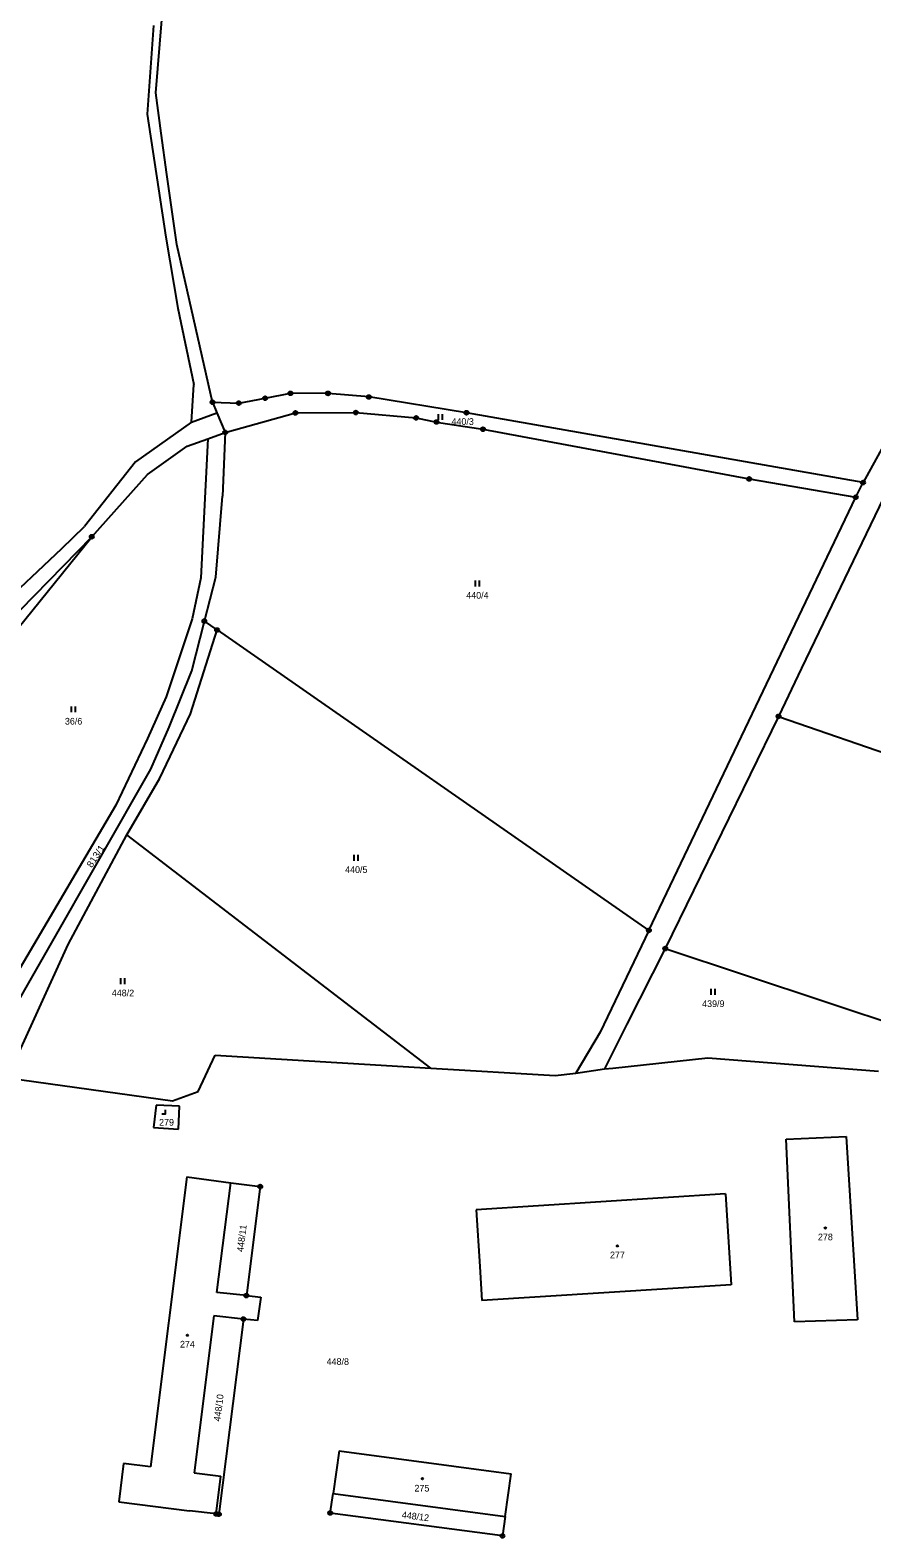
# Model space of a CAD drawing. Extents: x -739410 to -735662, y -942282 to -940043.
# Drawn here: x -737598.7 to -737384.4, y -941577.7 to -941193.9 of the extents above; entities that cross this region are included whole.
import ezdxf
from ezdxf.enums import TextEntityAlignment as Align

# ---------------------------------------------------------------- set-up
doc = ezdxf.new("R2010")
doc.units = 0
doc.header["$LTSCALE"] = 0.68
for name, color, linetype, lineweight in [('1', 7, 'Continuous', 25), ('3', 7, 'Continuous', 25), ('5', 7, 'Continuous', 25), ('8', 7, 'Continuous', 25)]:
    doc.layers.add(name, color=color, linetype=linetype, lineweight=lineweight)
doc.layers.add('2', color=7, linetype='Continuous')

msp = doc.modelspace()

# ---------------------------------------------------------------- linework, layer by layer
at = {"layer": '1'}
for p, q in [((-737567.25, -941192.75), (-737568.89, -941215.34)), ((-737566.68, -941209.91), (-737565.18, -941191.33)), ((-737565.29, -941220.14), (-737566.68, -941209.91)), ((-737568.89, -941215.34), (-737564.15, -941246.6)), ((-737563.9, -941230.66), (-737565.29, -941220.14)), ((-737561.32, -941248.49), (-737563.9, -941230.66)), ((-737564.15, -941246.6), (-737561.08, -941264.67)), ((-737552.23, -941288.66), (-737561.32, -941248.49)), ((-737561.08, -941264.67), (-737557, -941284.11)), ((-737557.62, -941293.73), (-737557, -941284.11)), ((-737538.85, -941287.63), (-737532.42, -941286.38)), ((-737522.84, -941286.4), (-737532.42, -941286.38)), ((-737512.43, -941287.32), (-737522.84, -941286.4)), ((-737552.23, -941288.66), (-737551.11, -941291.34)), ((-737552.23, -941288.66), (-737545.56, -941288.87)), ((-737545.56, -941288.87), (-737538.85, -941287.63)), ((-737487.61, -941291.32), (-737512.43, -941287.32)), ((-737557.62, -941293.73), (-737571.83, -941303.81)), ((-737557.62, -941293.73), (-737551.11, -941291.34)), ((-737551.11, -941291.34), (-737549.01, -941296.33)), ((-737549.01, -941296.33), (-737531.14, -941291.37)), ((-737531.14, -941291.37), (-737515.75, -941291.28)), ((-737515.75, -941291.28), (-737500.42, -941292.65)), ((-737500.42, -941292.65), (-737495.23, -941293.69)), ((-737495.23, -941293.69), (-737483.4, -941295.53)), ((-737386.64, -941309.11), (-737487.61, -941291.32)), ((-737558.7, -941299.8), (-737553.41, -941297.93)), ((-737553.41, -941297.93), (-737555.2, -941333.38)), ((-737553.41, -941297.93), (-737549.01, -941296.33)), ((-737549.01, -941296.33), (-737549.68, -941312.57)), ((-737483.4, -941295.53), (-737415.63, -941308.18)), ((-737380.49, -941297.99), (-737386.64, -941309.11)), ((-737568.81, -941307.04), (-737558.7, -941299.8)), ((-737571.83, -941303.81), (-737584.85, -941320.25)), ((-737582.99, -941322.88), (-737568.81, -941307.04)), ((-737415.63, -941308.18), (-737388.51, -941312.84)), ((-737388.51, -941312.84), (-737386.64, -941309.11)), ((-737551.42, -941333.21), (-737549.68, -941312.57)), ((-737441.17, -941423.08), (-737388.51, -941312.84)), ((-737381.43, -941312.98), (-737402.36, -941356.33)), ((-737590.57, -941325.9), (-737584.85, -941320.25)), ((-737604.75, -941345.26), (-737582.99, -941322.88)), ((-737603.59, -941348.41), (-737582.99, -941322.88)), ((-737608.18, -941342.43), (-737590.57, -941325.9)), ((-737555.2, -941333.38), (-737557.44, -941343.8)), ((-737554.32, -941344.36), (-737551.42, -941333.21)), ((-737557.44, -941343.8), (-737564.06, -941363.65)), ((-737557.52, -941357.03), (-737554.32, -941344.36)), ((-737551.08, -941346.62), (-737554.32, -941344.36)), ((-737557.82, -941367.93), (-737551.08, -941346.62)), ((-737551.08, -941346.62), (-737441.17, -941423.08)), ((-737563.32, -941371.36), (-737557.52, -941357.03)), ((-737402.36, -941356.33), (-737408.16, -941368.6)), ((-737564.06, -941363.65), (-737568.77, -941374.27)), ((-737567.98, -941382.05), (-737563.32, -941371.36)), ((-737565.69, -941384.32), (-737557.82, -941367.93)), ((-737408.16, -941368.6), (-737436.99, -941427.7)), ((-737408.16, -941368.6), (-737318.79, -941399.47)), ((-737568.77, -941374.27), (-737576.89, -941391.18)), ((-737606.95, -941450.23), (-737567.98, -941382.05)), ((-737574.08, -941398.77), (-737565.69, -941384.32)), ((-737576.89, -941391.18), (-737601.21, -941432.59)), ((-737589.02, -941426.68), (-737574.08, -941398.77)), ((-737496.66, -941458.16), (-737574.08, -941398.77)), ((-737441.17, -941423.08), (-737453.54, -941448.98)), ((-737604.45, -941460.6), (-737589.02, -941426.68)), ((-737436.99, -941427.7), (-737446.76, -941446.95)), ((-737436.99, -941427.7), (-737374.65, -941448.39)), ((-737446.76, -941446.95), (-737452.43, -941458.32)), ((-737453.54, -941448.98), (-737459.74, -941459.43)), ((-737555.92, -941464.07), (-737551.58, -941454.86)), ((-737551.58, -941454.86), (-737496.66, -941458.16)), ((-737450.31, -941458.14), (-737426.13, -941455.54)), ((-737426.13, -941455.54), (-737382.68, -941458.93)), ((-737496.66, -941458.16), (-737465.03, -941460.03)), ((-737452.43, -941458.32), (-737450.31, -941458.14)), ((-737604.45, -941460.6), (-737562.44, -941466.42)), ((-737562.44, -941466.42), (-737555.92, -941464.07)), ((-737566.59, -941467.59), (-737567.26, -941473.26)), ((-737560.66, -941467.84), (-737566.59, -941467.59)), ((-737560.89, -941473.71), (-737560.66, -941467.84)), ((-737567.26, -941473.26), (-737560.89, -941473.71)), ((-737406.26, -941476.19), (-737390.95, -941475.55)), ((-737404.13, -941522.75), (-737406.26, -941476.19)), ((-737390.95, -941475.55), (-737388.09, -941522.19)), ((-737558.77, -941485.83), (-737568.02, -941559.59)), ((-737558.77, -941485.83), (-737547.55, -941487.33)), ((-737551.11, -941515.24), (-737547.55, -941487.33)), ((-737547.55, -941487.33), (-737540.09, -941488.29)), ((-737540.09, -941488.29), (-737543.63, -941516.03)), ((-737421.65, -941490.16), (-737485.13, -941494.18)), ((-737421.65, -941490.16), (-737420.2, -941513.26)), ((-737485.13, -941494.18), (-737484.21, -941508.62)), ((-737484.21, -941508.62), (-737483.68, -941517.28)), ((-737420.2, -941513.26), (-737483.68, -941517.28)), ((-737543.63, -941516.03), (-737551.11, -941515.24)), ((-737543.63, -941516.03), (-737539.97, -941516.41)), ((-737539.97, -941516.41), (-737540.76, -941522.41)), ((-737551.87, -941521.2), (-737556.95, -941561.15)), ((-737544.38, -941522.02), (-737551.87, -941521.2)), ((-737544.38, -941522.02), (-737550.63, -941571.69)), ((-737540.76, -941522.41), (-737544.38, -941522.02)), ((-737388.09, -941522.19), (-737404.13, -941522.75)), ((-737519.99, -941555.56), (-737521.56, -941566.38)), ((-737519.99, -941555.56), (-737476.2, -941561.43)), ((-737574.9, -941558.76), (-737576.11, -941568.51)), ((-737568.02, -941559.59), (-737574.9, -941558.76)), ((-737556.95, -941561.15), (-737550.14, -941562.02)), ((-737551.28, -941571.61), (-737550.14, -941562.02)), ((-737477.77, -941572.25), (-737476.2, -941561.43)), ((-737522.28, -941571.37), (-737521.56, -941566.38)), ((-737521.56, -941566.38), (-737477.77, -941572.25)), ((-737576.11, -941568.51), (-737558.08, -941570.8)), ((-737551.28, -941571.61), (-737558.08, -941570.8)), ((-737550.63, -941571.69), (-737551.28, -941571.61)), ((-737478.44, -941577.19), (-737522.28, -941571.37)), ((-737477.77, -941572.25), (-737478.44, -941577.19))]:
    msp.add_line(p, q, dxfattribs=at)
msp.add_lwpolyline([(-737465.03, -941460.03), (-737459.74, -941459.43), (-737452.43, -941458.32)], dxfattribs=at)
at = {"layer": '3'}
for p, q in [((-737494.711, -941293.15), (-737494.711, -941291.65)), ((-737493.71, -941293.15), (-737493.71, -941291.65)), ((-737485.321, -941335.51), (-737485.321, -941334.01)), ((-737484.32, -941335.51), (-737484.32, -941334.01)), ((-737588.121, -941367.57), (-737588.121, -941366.07)), ((-737587.12, -941367.57), (-737587.12, -941366.07)), ((-737516.161, -941405.34), (-737516.161, -941403.84)), ((-737515.16, -941405.34), (-737515.16, -941403.84)), ((-737575.551, -941436.74), (-737575.551, -941435.24)), ((-737574.55, -941436.74), (-737574.55, -941435.24)), ((-737425.281, -941439.47), (-737425.281, -941437.97)), ((-737424.28, -941439.47), (-737424.28, -941437.97))]:
    msp.add_line(p, q, dxfattribs=at)
msp.add_lwpolyline([(-737565.171, -941469.78), (-737564.17, -941469.78), (-737564.17, -941468.78)], dxfattribs=at)
at = {"layer": '5'}
for centre in [(-737396.2468, -941498.8292), (-737449.1768, -941503.3992), (-737558.6368, -941526.1292), (-737498.8068, -941562.6292)]:
    msp.add_circle(centre, 0.175, dxfattribs=at)
at = {"layer": '8'}
for centre, radius in [((-737532.42, -941286.3799), 0.5), ((-737532.42, -941286.3799), 0.0303), ((-737522.84, -941286.3999), 0.5), ((-737522.84, -941286.3999), 0.0303), ((-737512.43, -941287.3199), 0.5), ((-737552.23, -941288.6599), 0.5), ((-737552.23, -941288.6599), 0.0303), ((-737545.56, -941288.8699), 0.5), ((-737545.56, -941288.8699), 0.0303), ((-737538.85, -941287.6299), 0.5), ((-737538.85, -941287.6299), 0.0303), ((-737531.14, -941291.3699), 0.5), ((-737515.75, -941291.2799), 0.5), ((-737512.43, -941287.3199), 0.0303), ((-737487.61, -941291.3199), 0.5), ((-737531.14, -941291.3699), 0.0303), ((-737515.75, -941291.2799), 0.0303), ((-737500.42, -941292.6499), 0.5), ((-737500.42, -941292.6499), 0.0303), ((-737495.23, -941293.6899), 0.5), ((-737495.23, -941293.6899), 0.0303), ((-737487.61, -941291.3199), 0.0303), ((-737549.01, -941296.3299), 0.5), ((-737549.01, -941296.3299), 0.0303), ((-737483.4, -941295.5299), 0.5), ((-737483.4, -941295.5299), 0.0303), ((-737415.63, -941308.1799), 0.5), ((-737415.63, -941308.1799), 0.0303), ((-737386.64, -941309.1099), 0.5), ((-737386.64, -941309.1099), 0.0303), ((-737388.51, -941312.8399), 0.5), ((-737388.51, -941312.8399), 0.0303), ((-737582.99, -941322.8799), 0.5), ((-737582.99, -941322.8799), 0.0303), ((-737554.32, -941344.3599), 0.5), ((-737554.32, -941344.3599), 0.0303), ((-737551.08, -941346.6199), 0.5), ((-737551.08, -941346.6199), 0.0303), ((-737408.16, -941368.5999), 0.5), ((-737408.16, -941368.5999), 0.0303), ((-737441.17, -941423.0799), 0.5), ((-737441.17, -941423.0799), 0.0303), ((-737436.99, -941427.6999), 0.5), ((-737436.99, -941427.6999), 0.0303), ((-737540.09, -941488.2899), 0.5), ((-737540.09, -941488.2899), 0.0303), ((-737543.63, -941516.0299), 0.5), ((-737543.63, -941516.0299), 0.0303), ((-737544.38, -941522.0199), 0.5), ((-737544.38, -941522.0199), 0.0303), ((-737522.28, -941571.3699), 0.5), ((-737551.28, -941571.6099), 0.5), ((-737551.28, -941571.6099), 0.0303), ((-737550.63, -941571.6899), 0.5), ((-737550.63, -941571.6899), 0.0303), ((-737522.28, -941571.3699), 0.0303), ((-737478.44, -941577.1899), 0.5), ((-737478.44, -941577.1899), 0.0303)]:
    msp.add_circle(centre, radius, dxfattribs=at)

# ---------------------------------------------------------------- texts
at = {"layer": '2'}
for s, p in [('440/3', (-737488.57, -941294.425)), ('440/4', (-737484.81, -941338.635)), ('36/6', (-737587.609, -941370.695)), ('440/5', (-737515.65, -941408.465)), ('448/2', (-737575.04, -941439.865)), ('439/9', (-737424.77, -941442.595)), ('279', (-737563.949, -941472.775)), ('278', (-737396.239, -941501.955)), ('277', (-737449.169, -941506.525)), ('274', (-737558.629, -941529.255)), ('448/8', (-737520.35, -941533.675)), ('275', (-737498.949, -941565.905))]:
    msp.add_text(s, height=1.7, dxfattribs=at).set_placement(p, align=Align.CENTER)
at = {"layer": '2', "width": 1.1}
msp.add_text('813/1', height=1.7, rotation=57, dxfattribs=at).set_placement((-737581.2904, -941404.6559), align=Align.CENTER)
at = {"layer": '2'}
for s, rotation, p in [('448/11', 83, (-737543.9611, -941501.5491)), ('448/10', 83, (-737549.8311, -941544.6791)), ('448/12', 353, (-737500.6991, -941573.0479))]:
    msp.add_text(s, height=1.7, rotation=rotation, dxfattribs=at).set_placement(p, align=Align.CENTER)

doc.saveas('drawing.dxf')
